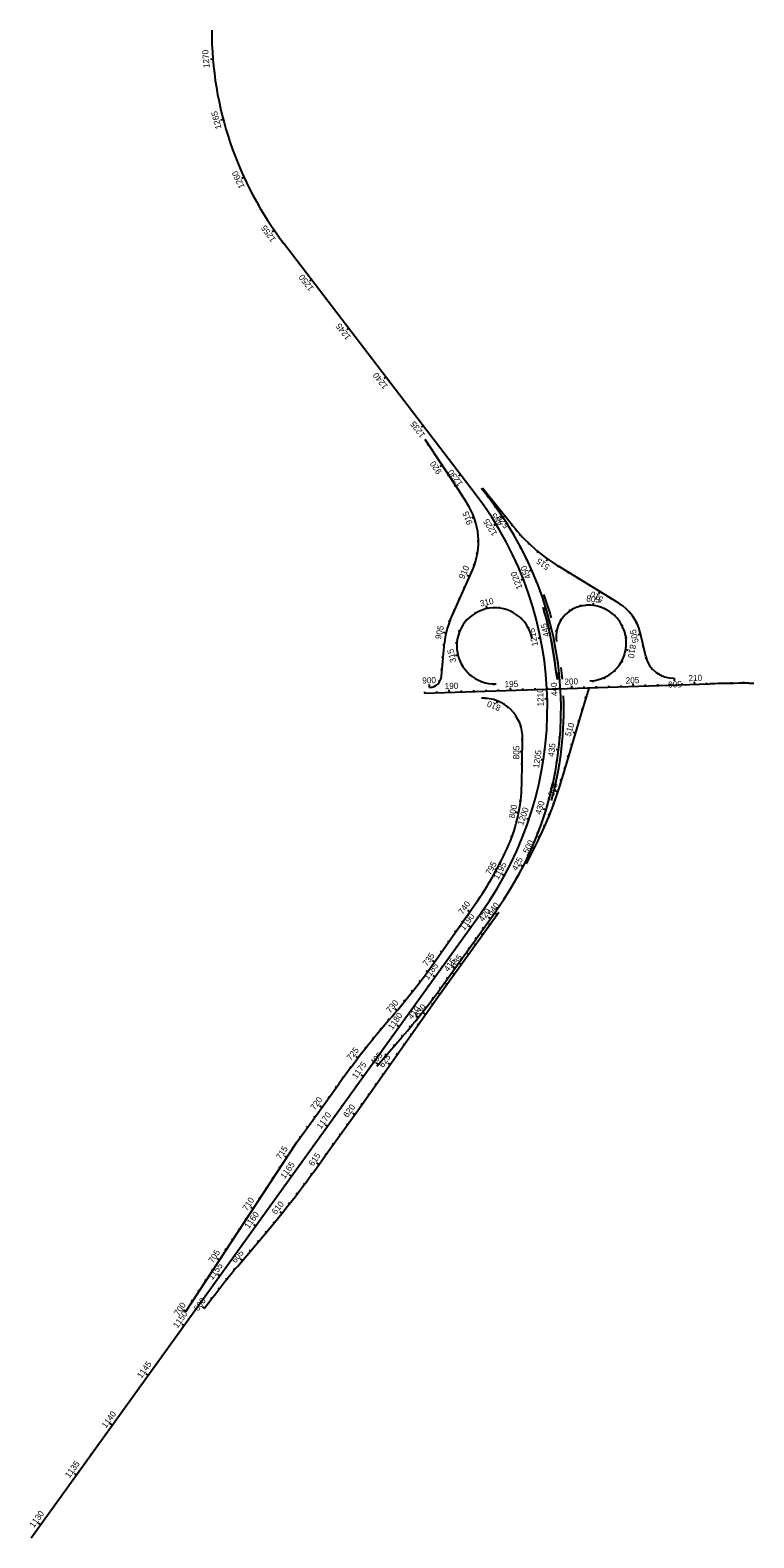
# Model space of a CAD drawing. Extents: x 448091 to 665917, y 1461380 to 1587607.
# Drawn here: x 571758 to 577655, y 1543048 to 1555334 of the extents above; entities that cross this region are included whole.
import ezdxf

# ---------------------------------------------------------------- set-up
doc = ezdxf.new("R2010")
doc.units = 0
doc.layers.add('TextShtNo', color=7, linetype='Continuous')
doc.layers.add('TextTitle', color=7, linetype='Continuous')

msp = doc.modelspace()

# ---------------------------------------------------------------- linework, layer by layer
at = {"layer": 'TextShtNo'}
for p, q in [((575384, 1551556), (573826, 1553594)), ((575247, 1551587), (574976, 1551997)), ((575689, 1551296), (575445, 1551602)), ((575317, 1551481), (575247, 1551587)), ((575506, 1551508), (575438, 1551597)), ((575180, 1550525), (575362, 1550933)), ((576555, 1550664), (576062, 1550966)), ((576286, 1550647), (576286, 1550647)), ((576775, 1550229), (576728, 1550427)), ((575109, 1550068), (575133, 1550342)), ((575969, 1549963), (577296, 1550006)), ((576054, 1550042), (576044, 1550101)), ((576046, 1550102), (576056, 1550042)), ((577615, 1550012), (577655, 1550012)), ((574970, 1549931), (575969, 1549963)), ((576257, 1549784), (576315, 1549979)), ((576095, 1549244), (576257, 1549784)), ((575764, 1549183), (575771, 1549560)), ((575903, 1548746), (575800, 1548541)), ((575052, 1547738), (575385, 1548212)), ((575115, 1547543), (575558, 1548161)), ((571766, 1543048), (575433, 1548142)), ((575064, 1547431), (575578, 1548147)), ((574429, 1546531), (575064, 1547431)), ((574583, 1546892), (574789, 1547130)), ((574166, 1546597), (574276, 1546749)), ((573991, 1546353), (574166, 1546597)), ((574195, 1546206), (574370, 1546450)), ((574370, 1546450), (574429, 1546531)), ((573932, 1546272), (573991, 1546353)), ((573025, 1544892), (573932, 1546272)), ((574077, 1546042), (574195, 1546206)), ((573450, 1545262), (573700, 1545558))]:
    msp.add_line(p, q, dxfattribs=at)
for centre, radius, start, end in [((576102, 1555334), 2865, 180.007, 217.4), ((574838, 1551165), 573, 336.0266, 33.3932), ((573108, 1549816), 2865, 324.2497, 37.4), ((573272, 1549800), 2812, 324.3687, 37.4), ((576809, 1552188), 1432, 218.5389, 238.5389), ((575544, 1550316), 310, 11.6008, 271.8444), ((573192, 1549807), 2866, 5.8885, 16.6427), ((573192, 1549807), 2868, 5.8883, 16.6427), ((573289, 1549746), 2832, 16.3712, 20.4488), ((576304, 1550387), 260, 93.9912, 188.0577), ((576307, 1550339), 309, 271.9781, 93.9912), ((576356, 1550338), 382, 13.3478, 58.5389), ((575704, 1550292), 573, 156.0267, 175.0267), ((573272, 1549800), 2834, 4.9716, 6.8992), ((576998, 1550283), 230, 193.3478, 271.8444), ((575010, 1550077), 100, 271.8444, 355.0269), ((577665, 1538554), 11458, 90.2522, 91.8444), ((575446, 1549565), 325, 358.9999, 91.8446), ((573272, 1549800), 2834, 344.7947, 2.1944), ((574491, 1549205), 1273, 336.1833, 358.9999), ((573361, 1550012), 2840, 333.5239, 344.3121), ((573108, 1549816), 2785, 324.8485, 336.2966), ((570367, 1551037), 5730, 319.251, 324.8485), ((570458, 1550881), 5730, 319.1078, 324.3687), ((580768, 1542075), 8000, 139.251, 144.2497), ((567584, 1550716), 8000, 319.8565, 324.2497), ((577830, 1541568), 5730, 139.8565, 144.2497)]:
    msp.add_arc(centre, radius, start, end, dxfattribs=at)
at = {"layer": 'TextTitle'}
for p, q in [((573237, 1555296), (573232, 1555296)), ((573240, 1555196), (573235, 1555196)), ((573247, 1555096), (573227, 1555095)), ((573257, 1554997), (573252, 1554996)), ((573270, 1554898), (573265, 1554897)), ((573287, 1554799), (573282, 1554798)), ((573307, 1554701), (573303, 1554700)), ((573331, 1554604), (573312, 1554599)), ((573358, 1554508), (573354, 1554507)), ((573389, 1554413), (573384, 1554411)), ((573423, 1554319), (573418, 1554317)), ((573460, 1554226), (573455, 1554224)), ((573500, 1554134), (573482, 1554126)), ((573543, 1554044), (573539, 1554042)), ((573590, 1553956), (573586, 1553953)), ((573640, 1553869), (573635, 1553866)), ((573692, 1553784), (573688, 1553781)), ((573748, 1553701), (573731, 1553689)), ((573806, 1553620), (573802, 1553617)), ((573867, 1553540), (573863, 1553537)), ((573928, 1553461), (573924, 1553458)), ((573988, 1553381), (573984, 1553378)), ((574049, 1553302), (574033, 1553290)), ((574110, 1553222), (574106, 1553219)), ((574171, 1553143), (574167, 1553140)), ((574231, 1553063), (574227, 1553060)), ((574292, 1552984), (574288, 1552981)), ((574353, 1552905), (574337, 1552892)), ((574413, 1552825), (574410, 1552822)), ((574474, 1552746), (574470, 1552743)), ((574535, 1552666), (574531, 1552663)), ((574596, 1552587), (574592, 1552584)), ((574656, 1552507), (574641, 1552495)), ((574717, 1552428), (574713, 1552425)), ((574778, 1552348), (574774, 1552345)), ((574839, 1552269), (574835, 1552266)), ((574899, 1552190), (574895, 1552187)), ((574960, 1552110), (574944, 1552098)), ((575021, 1552031), (575017, 1552028)), ((575003, 1551957), (574994, 1551951)), ((575058, 1551873), (575049, 1551867)), ((575082, 1551951), (575078, 1551948)), ((575142, 1551872), (575138, 1551869)), ((575113, 1551790), (575096, 1551778)), ((575203, 1551792), (575199, 1551789)), ((575168, 1551706), (575159, 1551700)), ((575223, 1551623), (575214, 1551617)), ((575264, 1551713), (575248, 1551701)), ((575325, 1551633), (575321, 1551630)), ((575278, 1551539), (575269, 1551533)), ((575385, 1551554), (575381, 1551551)), ((575438, 1551597), (575434, 1551593)), ((575487, 1551533), (575478, 1551527)), ((575501, 1551532), (575492, 1551525)), ((575332, 1551455), (575323, 1551450)), ((575375, 1551365), (575356, 1551358)), ((575445, 1551473), (575440, 1551471)), ((575501, 1551391), (575497, 1551388)), ((575547, 1551453), (575538, 1551447)), ((575563, 1551454), (575555, 1551447)), ((575604, 1551371), (575587, 1551360)), ((575625, 1551376), (575609, 1551363)), ((575402, 1551269), (575391, 1551267)), ((575555, 1551306), (575537, 1551296)), ((575659, 1551287), (575650, 1551282)), ((575688, 1551297), (575679, 1551291)), ((575411, 1551169), (575400, 1551169)), ((575605, 1551220), (575601, 1551218)), ((575653, 1551132), (575648, 1551130)), ((575710, 1551202), (575701, 1551196)), ((575752, 1551221), (575745, 1551214)), ((575758, 1551114), (575749, 1551109)), ((575822, 1551150), (575815, 1551142)), ((575403, 1551070), (575392, 1551072)), ((575697, 1551043), (575692, 1551040)), ((575804, 1551025), (575794, 1551020)), ((575897, 1551084), (575890, 1551075)), ((575977, 1551023), (575964, 1551006)), ((575339, 1550881), (575320, 1550890)), ((575378, 1550973), (575368, 1550977)), ((575738, 1550952), (575734, 1550950)), ((575846, 1550934), (575827, 1550926)), ((576060, 1550967), (576054, 1550958)), ((576145, 1550915), (576140, 1550906)), ((575298, 1550790), (575288, 1550794)), ((575776, 1550859), (575758, 1550852)), ((575811, 1550765), (575806, 1550764)), ((575884, 1550842), (575874, 1550838)), ((575920, 1550748), (575910, 1550745)), ((576230, 1550863), (576225, 1550854)), ((576316, 1550811), (576310, 1550802)), ((576401, 1550759), (576390, 1550741)), ((575258, 1550698), (575248, 1550703)), ((575481, 1550619), (575477, 1550639)), ((575580, 1550624), (575581, 1550634)), ((575843, 1550670), (575838, 1550669)), ((575952, 1550654), (575941, 1550650)), ((576246, 1550641), (576244, 1550651)), ((576346, 1550645), (576348, 1550665)), ((576441, 1550617), (576446, 1550626)), ((576486, 1550707), (576481, 1550697)), ((576571, 1550654), (576565, 1550645)), ((575176, 1550516), (575166, 1550520)), ((575217, 1550607), (575207, 1550611)), ((575311, 1550520), (575304, 1550527)), ((575388, 1550584), (575383, 1550592)), ((575676, 1550596), (575680, 1550605)), ((575758, 1550540), (575765, 1550547)), ((575871, 1550574), (575866, 1550573)), ((575980, 1550558), (575970, 1550555)), ((576086, 1550529), (576078, 1550535)), ((576155, 1550601), (576150, 1550609)), ((576523, 1550560), (576530, 1550567)), ((576646, 1550587), (576638, 1550580)), ((576700, 1550504), (576691, 1550499)), ((575146, 1550421), (575125, 1550425)), ((575258, 1550436), (575249, 1550440)), ((575818, 1550461), (575827, 1550465)), ((575896, 1550478), (575891, 1550476)), ((575917, 1550380), (575897, 1550376)), ((576006, 1550461), (575985, 1550456)), ((576049, 1550437), (576039, 1550439)), ((576582, 1550480), (576591, 1550485)), ((576613, 1550385), (576623, 1550387)), ((576732, 1550409), (576712, 1550405)), ((575131, 1550322), (575121, 1550323)), ((575235, 1550339), (575225, 1550340)), ((575935, 1550282), (575930, 1550281)), ((576027, 1550363), (576017, 1550361)), ((576046, 1550265), (576035, 1550263)), ((576612, 1550286), (576632, 1550282)), ((576755, 1550312), (576744, 1550310)), ((575123, 1550222), (575112, 1550223)), ((575244, 1550240), (575224, 1550235)), ((575283, 1550149), (575275, 1550143)), ((575949, 1550183), (575945, 1550182)), ((576061, 1550166), (576050, 1550165)), ((576579, 1550192), (576588, 1550187)), ((576779, 1550215), (576768, 1550212)), ((576827, 1550129), (576819, 1550121)), ((575095, 1550025), (575086, 1550031)), ((575114, 1550122), (575103, 1550123)), ((575350, 1550074), (575343, 1550067)), ((575436, 1550025), (575433, 1550016)), ((575534, 1550006), (575534, 1549996)), ((575961, 1550083), (575956, 1550083)), ((576072, 1550067), (576061, 1550066)), ((576340, 1550031), (576341, 1550021)), ((576436, 1550057), (576440, 1550048)), ((576519, 1550113), (576525, 1550106)), ((576673, 1549986), (576672, 1550007)), ((576908, 1550071), (576904, 1550061)), ((576973, 1549996), (576972, 1550006)), ((577006, 1550053), (577006, 1550032)), ((577073, 1549999), (577072, 1550010)), ((577173, 1550002), (577172, 1550023)), ((577273, 1550005), (577272, 1550016)), ((577373, 1550008), (577372, 1550019)), ((577473, 1550010), (577472, 1550021)), ((577573, 1550012), (577573, 1550022)), ((574974, 1549931), (574974, 1549942)), ((575013, 1549979), (575012, 1550001)), ((575013, 1549977), (575012, 1549987)), ((575074, 1549934), (575073, 1549945)), ((575174, 1549938), (575173, 1549958)), ((575274, 1549941), (575273, 1549952)), ((575374, 1549944), (575373, 1549955)), ((575470, 1549889), (575469, 1549879)), ((575474, 1549947), (575473, 1549958)), ((575574, 1549951), (575573, 1549961)), ((575674, 1549954), (575673, 1549975)), ((575773, 1549957), (575773, 1549968)), ((575873, 1549960), (575873, 1549971)), ((575972, 1549884), (575952, 1549883)), ((575968, 1549984), (575963, 1549983)), ((575973, 1549963), (575973, 1549974)), ((576080, 1549967), (576069, 1549967)), ((576073, 1549967), (576073, 1549977)), ((576173, 1549970), (576173, 1549991)), ((576273, 1549973), (576273, 1549984)), ((576289, 1549893), (576279, 1549896)), ((576373, 1549976), (576373, 1549987)), ((576473, 1549980), (576473, 1549990)), ((576573, 1549983), (576573, 1549993)), ((576773, 1549989), (576773, 1550000)), ((576873, 1549992), (576873, 1550003)), ((575567, 1549867), (575559, 1549848)), ((575652, 1549816), (575646, 1549808)), ((575973, 1549784), (575968, 1549784)), ((576084, 1549867), (576073, 1549867)), ((576084, 1549767), (576074, 1549767)), ((576261, 1549797), (576250, 1549800)), ((575719, 1549741), (575710, 1549736)), ((575759, 1549651), (575750, 1549648)), ((575970, 1549684), (575965, 1549684)), ((576081, 1549667), (576071, 1549668)), ((576232, 1549701), (576222, 1549704)), ((575770, 1549552), (575760, 1549552)), ((575767, 1549611), (575762, 1549611)), ((575964, 1549584), (575959, 1549584)), ((576075, 1549568), (576064, 1549568)), ((576174, 1549510), (576164, 1549513)), ((576203, 1549605), (576183, 1549611)), ((575769, 1549452), (575749, 1549452)), ((575954, 1549484), (575949, 1549485)), ((576065, 1549468), (576044, 1549471)), ((576146, 1549414), (576135, 1549417)), ((575767, 1549352), (575757, 1549352)), ((575924, 1549287), (575919, 1549288)), ((575941, 1549385), (575921, 1549388)), ((576034, 1549270), (576024, 1549272)), ((576051, 1549369), (576041, 1549371)), ((576117, 1549318), (576107, 1549321)), ((575763, 1549152), (575753, 1549152)), ((575765, 1549252), (575755, 1549252)), ((575904, 1549189), (575899, 1549190)), ((576014, 1549173), (576003, 1549175)), ((576088, 1549222), (576078, 1549225)), ((575755, 1549052), (575745, 1549053)), ((575880, 1549092), (575875, 1549093)), ((575990, 1549076), (575979, 1549078)), ((576026, 1549032), (576016, 1549036)), ((576059, 1549127), (576039, 1549133)), ((575739, 1548953), (575719, 1548957)), ((575823, 1548900), (575804, 1548906)), ((575853, 1548995), (575848, 1548997)), ((575962, 1548979), (575942, 1548985)), ((575990, 1548939), (575980, 1548943)), ((575715, 1548856), (575706, 1548859)), ((575789, 1548806), (575785, 1548808)), ((575897, 1548790), (575887, 1548794)), ((575931, 1548884), (575921, 1548888)), ((575951, 1548847), (575941, 1548852)), ((575646, 1548669), (575642, 1548671)), ((575684, 1548761), (575675, 1548765)), ((575752, 1548713), (575748, 1548715)), ((575863, 1548667), (575845, 1548676)), ((575860, 1548698), (575850, 1548702)), ((575908, 1548757), (575898, 1548761)), ((575603, 1548578), (575599, 1548580)), ((575669, 1548531), (575665, 1548533)), ((575712, 1548621), (575708, 1548623)), ((575819, 1548606), (575809, 1548611)), ((575819, 1548578), (575809, 1548582)), ((575557, 1548490), (575544, 1548496)), ((575623, 1548443), (575605, 1548452)), ((575718, 1548411), (575713, 1548414)), ((575728, 1548428), (575718, 1548434)), ((575775, 1548517), (575756, 1548526)), ((575455, 1548317), (575452, 1548320)), ((575508, 1548403), (575504, 1548405)), ((575573, 1548356), (575569, 1548358)), ((575677, 1548342), (575668, 1548348)), ((575698, 1548376), (575693, 1548379)), ((575708, 1548394), (575703, 1548397)), ((575341, 1548150), (575324, 1548162)), ((575400, 1548234), (575397, 1548237)), ((575465, 1548187), (575461, 1548190)), ((575521, 1548270), (575517, 1548273)), ((575568, 1548175), (575559, 1548181)), ((575624, 1548257), (575615, 1548263)), ((575284, 1548068), (575275, 1548074)), ((575407, 1548106), (575403, 1548109)), ((575509, 1548093), (575493, 1548106)), ((575504, 1548045), (575496, 1548051)), ((575562, 1548126), (575546, 1548138)), ((575226, 1547986), (575217, 1547992)), ((575290, 1547943), (575286, 1547946)), ((575349, 1548025), (575333, 1548036)), ((575393, 1547931), (575384, 1547937)), ((575446, 1547964), (575437, 1547970)), ((575451, 1548012), (575442, 1548018)), ((575111, 1547823), (575102, 1547829)), ((575168, 1547904), (575160, 1547911)), ((575232, 1547862), (575228, 1547865)), ((575329, 1547801), (575321, 1547808)), ((575335, 1547850), (575326, 1547856)), ((575388, 1547883), (575379, 1547889)), ((575053, 1547741), (575036, 1547753)), ((575115, 1547700), (575111, 1547703)), ((575174, 1547781), (575170, 1547784)), ((575218, 1547687), (575201, 1547699)), ((575271, 1547720), (575254, 1547732)), ((575276, 1547768), (575268, 1547775)), ((574935, 1547579), (574927, 1547586)), ((574995, 1547660), (574986, 1547666)), ((575057, 1547619), (575041, 1547630)), ((575155, 1547557), (575146, 1547564)), ((575160, 1547606), (575151, 1547612)), ((575213, 1547639), (575204, 1547645)), ((574812, 1547422), (574804, 1547429)), ((574874, 1547500), (574866, 1547507)), ((574940, 1547456), (574936, 1547459)), ((574998, 1547538), (574994, 1547541)), ((575042, 1547444), (575034, 1547450)), ((575096, 1547476), (575088, 1547482)), ((575102, 1547525), (575093, 1547531)), ((574748, 1547345), (574732, 1547358)), ((574882, 1547375), (574877, 1547378)), ((574981, 1547313), (574964, 1547325)), ((574982, 1547365), (574973, 1547371)), ((575038, 1547395), (575030, 1547401)), ((574619, 1547192), (574611, 1547199)), ((574683, 1547269), (574675, 1547276)), ((574765, 1547213), (574748, 1547225)), ((574823, 1547294), (574819, 1547297)), ((574856, 1547209), (574848, 1547216)), ((574920, 1547286), (574903, 1547299)), ((574923, 1547231), (574914, 1547237)), ((574555, 1547115), (574547, 1547122)), ((574706, 1547132), (574702, 1547135)), ((574726, 1547057), (574718, 1547064)), ((574791, 1547133), (574783, 1547140)), ((574808, 1547068), (574799, 1547074)), ((574865, 1547150), (574857, 1547156)), ((574431, 1546958), (574415, 1546971)), ((574493, 1547037), (574484, 1547044)), ((574589, 1546970), (574585, 1546972)), ((574648, 1547051), (574644, 1547054)), ((574660, 1546981), (574652, 1546988)), ((574750, 1546986), (574741, 1546992)), ((574371, 1546879), (574362, 1546885)), ((574473, 1546807), (574456, 1546819)), ((574531, 1546888), (574527, 1546891)), ((574595, 1546906), (574579, 1546919)), ((574635, 1546823), (574626, 1546829)), ((574692, 1546904), (574676, 1546916)), ((574253, 1546717), (574244, 1546724)), ((574311, 1546798), (574302, 1546805)), ((574414, 1546726), (574410, 1546729)), ((574577, 1546741), (574568, 1546747)), ((574136, 1546555), (574119, 1546567)), ((574194, 1546636), (574185, 1546642)), ((574297, 1546564), (574293, 1546567)), ((574356, 1546645), (574352, 1546648)), ((574462, 1546578), (574453, 1546584)), ((574520, 1546659), (574511, 1546666)), ((574077, 1546474), (574069, 1546480)), ((574239, 1546483), (574235, 1546486)), ((574404, 1546496), (574387, 1546508)), ((573960, 1546312), (573952, 1546318)), ((574019, 1546393), (574010, 1546399)), ((574122, 1546320), (574118, 1546323)), ((574180, 1546401), (574164, 1546413)), ((574287, 1546334), (574278, 1546340)), ((574345, 1546415), (574337, 1546421)), ((573904, 1546229), (573895, 1546235)), ((574064, 1546239), (574059, 1546242)), ((574229, 1546253), (574220, 1546259)), ((573849, 1546146), (573832, 1546157)), ((573947, 1546077), (573943, 1546080)), ((574005, 1546158), (574001, 1546161)), ((574112, 1546090), (574095, 1546103)), ((574170, 1546172), (574161, 1546178)), ((573739, 1545978), (573730, 1545984)), ((573794, 1546062), (573785, 1546068)), ((573888, 1545996), (573872, 1546007)), ((574053, 1546009), (574045, 1546016)), ((573684, 1545895), (573675, 1545901)), ((573771, 1545833), (573767, 1545836)), ((573830, 1545915), (573826, 1545917)), ((573934, 1545849), (573925, 1545856)), ((573994, 1545929), (573985, 1545935)), ((573574, 1545728), (573557, 1545739)), ((573629, 1545811), (573620, 1545817)), ((573713, 1545752), (573709, 1545755)), ((573810, 1545692), (573794, 1545705)), ((573872, 1545770), (573864, 1545777)), ((573519, 1545644), (573510, 1545650)), ((573596, 1545590), (573580, 1545602)), ((573655, 1545671), (573651, 1545674)), ((573747, 1545614), (573738, 1545621)), ((573409, 1545477), (573400, 1545483)), ((573464, 1545561), (573455, 1545567)), ((573538, 1545509), (573534, 1545512)), ((573618, 1545461), (573610, 1545468)), ((573682, 1545538), (573674, 1545545)), ((573354, 1545394), (573345, 1545399)), ((573421, 1545346), (573417, 1545349)), ((573479, 1545428), (573475, 1545430)), ((573553, 1545385), (573545, 1545392)), ((573245, 1545226), (573236, 1545232)), ((573300, 1545310), (573282, 1545321)), ((573362, 1545265), (573358, 1545268)), ((573425, 1545232), (573416, 1545239)), ((573489, 1545308), (573473, 1545322)), ((573190, 1545143), (573181, 1545149)), ((573246, 1545103), (573242, 1545106)), ((573304, 1545184), (573288, 1545196)), ((573361, 1545154), (573353, 1545161)), ((573080, 1544976), (573071, 1544982)), ((573135, 1545059), (573126, 1545065)), ((573187, 1545022), (573183, 1545025)), ((573239, 1544996), (573230, 1545003)), ((573299, 1545076), (573291, 1545083)), ((573025, 1544892), (573008, 1544904)), ((573070, 1544859), (573066, 1544862)), ((573129, 1544941), (573125, 1544944)), ((573180, 1544916), (573163, 1544928)), ((573012, 1544778), (572996, 1544790)), ((572895, 1544616), (572891, 1544619)), ((572953, 1544697), (572949, 1544700)), ((572837, 1544535), (572833, 1544538)), ((572720, 1544373), (572704, 1544384)), ((572778, 1544454), (572774, 1544457)), ((572661, 1544291), (572657, 1544294)), ((572544, 1544129), (572540, 1544132)), ((572603, 1544210), (572599, 1544213)), ((572486, 1544048), (572482, 1544051)), ((572369, 1543886), (572365, 1543888)), ((572428, 1543967), (572411, 1543978)), ((572311, 1543804), (572307, 1543807)), ((572194, 1543642), (572190, 1543645)), ((572252, 1543723), (572248, 1543726)), ((572136, 1543561), (572119, 1543573)), ((572019, 1543399), (572015, 1543402)), ((572077, 1543480), (572073, 1543483)), ((571960, 1543317), (571956, 1543320)), ((571843, 1543155), (571827, 1543167)), ((571902, 1543236), (571898, 1543239)), ((571785, 1543074), (571781, 1543077))]:
    msp.add_line(p, q, dxfattribs=at)

# ---------------------------------------------------------------- texts
for s, rotation, p in [('1270', 94.7554, (573221, 1555027)), ('1265', 104.7554, (573318, 1554534)), ('1260', 114.7554, (573507, 1554057)), ('1255', 124.7554, (573762, 1553628)), ('1250', 127.4, (574072, 1553231)), ('1245', 127.4, (574374, 1552833)), ('1240', 127.4, (574676, 1552432)), ('1235', 127.4, (574981, 1552035)), ('920', 123.3932, (575115, 1551735)), ('1230', 127.4, (575286, 1551640)), ('915', 110.3915, (575365, 1551314)), ('455', 123.9794, (575611, 1551312)), ('520', 128.5389, (575664, 1551299)), ('1225', 121.3619, (575567, 1551231)), ('515', 144.4501, (575996, 1550970)), ('910', 66.0268, (575293, 1550855)), ('1220', 111.3619, (575771, 1550789)), ('450', 113.7919, (575841, 1550873)), ('510', 148.5389, (576434, 1550707)), ('310', 11.7696, (575429, 1550636)), ('805', 352.8844, (576288, 1550679)), ('445', 103.6044, (575992, 1550396)), ('905', 77.0252, (575105, 1550366)), ('1215', 101.362, (575897, 1550319)), ('505', 103.3478, (576718, 1550346)), ('315', 104.1822, (575231, 1550187)), ('810', 260.1718, (576647, 1550331)), ('900', 1.8444, (574954, 1550009)), ('190', 1.8444, (575136, 1549963)), ('195', 1.8444, (575624, 1549979)), ('440', 93.4169, (576056, 1549908)), ('200', 1.8444, (576112, 1549999)), ('205', 1.8444, (576611, 1550009)), ('500', 182.314, (577067, 1550030)), ('210', 1.8444, (577123, 1550028)), ('1210', 91.362, (575942, 1549823)), ('810', 158.0842, (575597, 1549829)), ('510', 73.285, (576162, 1549574)), ('435', 83.2294, (576027, 1549409)), ('805', 89, (575743, 1549391)), ('1205', 81.362, (575904, 1549317)), ('505', 71.834, (576024, 1549087)), ('800', 78.5767, (575705, 1548907)), ('430', 73.0419, (575919, 1548937)), ('1200', 71.362, (575774, 1548849)), ('500', 63.5239, (575815, 1548618)), ('795', 61.5623, (575509, 1548444)), ('1195', 61.362, (575572, 1548407)), ('425', 62.8544, (575724, 1548479)), ('740', 54.8485, (575283, 1548123)), ('420', 54.3687, (575449, 1548064)), ('640', 54.3687, (575519, 1548112)), ('1190', 54.2497, (575295, 1547993)), ('735', 54.8485, (574992, 1547701)), ('635', 54.3687, (575219, 1547687)), ('1185', 54.2497, (575000, 1547590)), ('415', 54.3687, (575166, 1547657)), ('730', 49.8783, (574691, 1547320)), ('1180', 54.2497, (574709, 1547184)), ('410', 51.1377, (574869, 1547269)), ('630', 54.7882, (574925, 1547283)), ('725', 52.3828, (574372, 1546933)), ('405', 49.1078, (574561, 1546894)), ('625', 54.7882, (574634, 1546875)), ('1175', 54.2497, (574416, 1546784)), ('720', 54.2497, (574077, 1546528)), ('620', 54.2497, (574345, 1546468)), ('1170', 54.2497, (574127, 1546374)), ('715', 56.679, (573799, 1546126)), ('1165', 54.2497, (573831, 1545969)), ('615', 54.2497, (574063, 1546072)), ('710', 56.679, (573525, 1545708)), ('1160', 54.2497, (573539, 1545563)), ('610', 51.0989, (573759, 1545679)), ('705', 56.679, (573247, 1545281)), ('605', 49.8565, (573430, 1545283)), ('1155', 54.2497, (573243, 1545145)), ('600', 54.2497, (573127, 1544890)), ('700', 56.679, (572968, 1544853)), ('1150', 54.2497, (572958, 1544752)), ('1145', 54.2497, (572664, 1544343)), ('1140', 54.2497, (572375, 1543937)), ('1135', 54.2497, (572078, 1543531)), ('1130', 54.2497, (571788, 1543125))]:
    msp.add_text(s, height=50, rotation=rotation, dxfattribs=at).set_placement(p)

doc.saveas('drawing.dxf')
